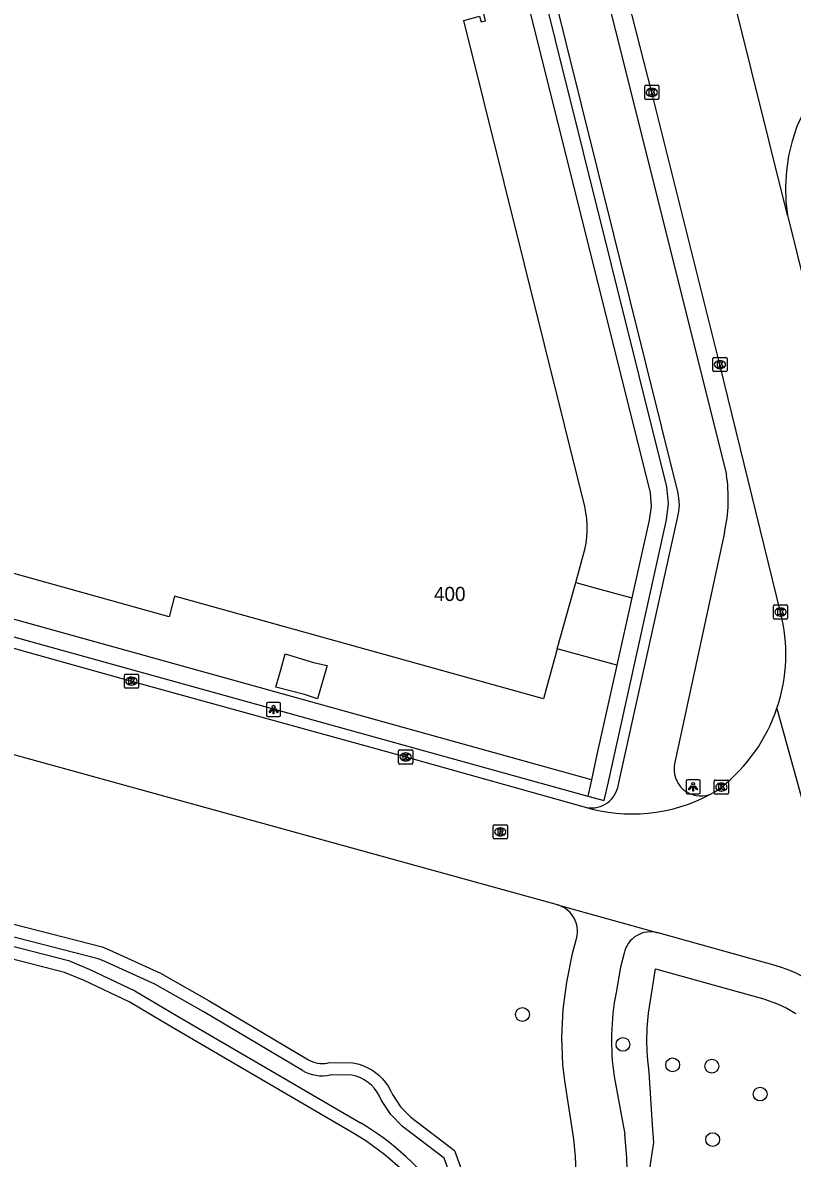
# Model space of a CAD drawing. Extents: x 161389 to 162585, y 388479 to 389761.
# Drawn here: x 162157.9 to 162212.3, y 388784.9 to 388865.1 of the extents above; entities that cross this region are included whole.
import ezdxf

# ---------------------------------------------------------------- set-up
doc = ezdxf.new("R2010")
doc.units = 0
for name, color, linetype in [('IMGEO_Berm_groen', 7, 'Continuous'), ('IMGEO_Boom', 7, 'Continuous'), ('IMGEO_Fietspad_gesloten', 7, 'Continuous'), ('IMGEO_Groenvoorziening', 7, 'Continuous'), ('IMGEO_Kolk', 7, 'Continuous'), ('IMGEO_Lage_trafo', 7, 'Continuous'), ('IMGEO_Lichtpunt', 7, 'Continuous'), ('IMGEO_Pand', 7, 'Continuous'), ('IMGEO_Pand_nummerreeks', 7, 'Continuous'), ('IMGEO_Rijbaan_lokaal_gesloten', 7, 'Continuous'), ('IMGEO_Rioolput', 7, 'Continuous'), ('IMGEO_Voetpad_open', 7, 'Continuous'), ('IMGEO_Waterloop', 7, 'Continuous')]:
    doc.layers.add(name, color=color, linetype=linetype)

msp = doc.modelspace()

# ---------------------------------------------------------------- linework, layer by layer
at = {"layer": 'IMGEO_Berm_groen'}
msp.add_lwpolyline([(162202.114, 388783.702), (162202.484, 388786.004), (162202.374, 388787.24), (162202.153, 388790.947), (162202.031, 388792.052), (162201.988, 388793.08), (162202.013, 388794.111), (162202.107, 388795.136), (162202.604, 388798.273), (162210.309, 388796.119), (162210.472, 388796.068), (162211.203, 388795.801), (162211.87, 388795.491), (162212.509, 388795.125)], dxfattribs=at)
at = {"layer": 'IMGEO_Boom'}
for centre in [(162193.192, 388795.045), (162200.292, 388792.933), (162203.803, 388791.484), (162206.574, 388791.398), (162209.981, 388789.423), (162206.633, 388786.205)]:
    msp.add_circle(centre, 0.489, dxfattribs=at)
at = {"layer": 'IMGEO_Fietspad_gesloten'}
for points in [[(162204.161, 388831.979), (162188.36, 388895.556)], [(162191.915, 388895.933), (162207.606, 388833.207)], [(162199.926, 388811.086), (162200.168, 388812.177), (162204.151, 388830.116)], [(162207.474, 388829.109), (162203.944, 388812.767)], [(162197.064, 388782.261), (162196.952, 388785.015), (162196.823, 388786.236), (162196.189, 388790.366), (162196.057, 388791.508), (162195.972, 388793.453), (162196.061, 388795.397), (162196.323, 388797.325), (162196.735, 388799.351), (162196.994, 388800.318), (162197.039, 388800.488), (162197.069, 388800.661), (162197.083, 388800.836), (162197.081, 388801.012), (162197.064, 388801.186), (162197.031, 388801.359), (162196.983, 388801.528), (162196.92, 388801.692), (162196.843, 388801.85), (162196.752, 388802), (162196.648, 388802.141), (162196.531, 388802.273), (162196.404, 388802.393), (162196.266, 388802.502), (162196.118, 388802.598), (162195.963, 388802.681), (162195.801, 388802.749), (162195.671, 388802.792)], [(162200.371, 388799.377), (162200.112, 388798.397), (162199.808, 388796.6)], [(162199.668, 388790.673), (162200.422, 388786.594)]]:
    msp.add_lwpolyline(points, dxfattribs=at)
for centre, radius, start, end in [((162196.527, 388831.513), 11.207, 347.61514, 8.69505), ((162200.631, 388831.066), 3.646, 344.89022, 14.49469), ((162205.803, 388812.381), 1.899, 168.25765, 289.15512), ((162198.075, 388811.547), 1.907, 254.42232, 346.00308), ((162202.261, 388798.955), 1.937, 74.75853, 167.40051), ((162217.393, 388793.219), 17.907, 169.1183, 188.17546), ((162163.354, 388782.698), 37.273, 345.55573, 5.99964)]:
    msp.add_arc(centre, radius, start, end, dxfattribs=at)
at = {"layer": 'IMGEO_Groenvoorziening'}
for points in [[(162133.461, 388807.522), (162163.504, 388799.815), (162163.994, 388799.622), (162167.615, 388797.975), (162171.074, 388796.012), (162178.078, 388791.853), (162178.229, 388791.773), (162178.386, 388791.706), (162178.548, 388791.653), (162178.715, 388791.616), (162178.884, 388791.593), (162179.055, 388791.586), (162179.225, 388791.594), (162179.394, 388791.617), (162179.528, 388791.646), (162181.221, 388791.631), (162181.333, 388791.61), (162181.653, 388791.53), (162181.964, 388791.422), (162182.265, 388791.286), (162182.552, 388791.124), (162182.823, 388790.937), (162183.077, 388790.727), (162183.311, 388790.495), (162183.523, 388790.242), (162183.711, 388789.972), (162183.875, 388789.686), (162184.013, 388789.387), (162184.582, 388788.521), (162185.306, 388787.78), (162188.39, 388785.424), (162193.632, 388770.975)], [(162184.71, 388784.039), (162183.465, 388785.137), (162182.128, 388786.119), (162181.291, 388786.646), (162168.421, 388794.144), (162165.402, 388795.939), (162162.235, 388797.457), (162160.843, 388798.018), (162131.299, 388805.617)]]:
    msp.add_lwpolyline(points, dxfattribs=at)
at = {"layer": 'IMGEO_Kolk'}
for p, q in [((162201.833, 388859.773), (162201.833, 388860.625)), ((162201.908, 388860.699), (162202.76, 388860.699)), ((162202.321, 388860.479), (162202.346, 388860.479)), ((162202.834, 388860.625), (162202.834, 388859.773)), ((162202.76, 388859.699), (162201.908, 388859.699)), ((162202.344, 388859.919), (162202.319, 388859.919)), ((162206.646, 388840.544), (162206.646, 388841.396)), ((162206.721, 388841.47), (162207.573, 388841.47)), ((162207.134, 388841.25), (162207.159, 388841.25)), ((162207.647, 388841.396), (162207.647, 388840.544)), ((162207.573, 388840.47), (162206.721, 388840.47)), ((162207.157, 388840.69), (162207.132, 388840.69)), ((162210.923, 388823.056), (162210.923, 388823.908)), ((162210.998, 388823.982), (162211.85, 388823.982)), ((162211.434, 388823.202), (162211.409, 388823.202)), ((162211.411, 388823.762), (162211.436, 388823.762)), ((162211.924, 388823.908), (162211.924, 388823.056)), ((162211.85, 388822.982), (162210.998, 388822.982)), ((162165.075, 388818.173), (162165.075, 388819.025)), ((162165.15, 388819.099), (162166.002, 388819.099)), ((162165.563, 388818.879), (162165.588, 388818.879)), ((162166.076, 388819.025), (162166.076, 388818.173)), ((162166.002, 388818.099), (162165.15, 388818.099)), ((162165.586, 388818.319), (162165.561, 388818.319)), ((162184.444, 388812.818), (162184.444, 388813.67)), ((162184.519, 388813.744), (162185.371, 388813.744)), ((162185.445, 388813.67), (162185.445, 388812.818)), ((162184.955, 388812.964), (162184.93, 388812.964)), ((162184.932, 388813.524), (162184.957, 388813.524)), ((162185.371, 388812.744), (162184.519, 388812.744)), ((162206.748, 388810.687), (162206.748, 388811.539)), ((162206.823, 388811.613), (162207.675, 388811.613)), ((162207.236, 388811.393), (162207.261, 388811.393)), ((162207.749, 388811.539), (162207.749, 388810.687)), ((162207.675, 388810.613), (162206.823, 388810.613)), ((162207.259, 388810.833), (162207.234, 388810.833))]:
    msp.add_line(p, q, dxfattribs=at)
for points in [[(162201.833, 388859.773), (162201.833, 388860.625)], [(162201.908, 388860.699), (162202.76, 388860.699)], [(162202.154, 388860.399), (162202.277, 388860.399), (162202.277, 388860.248), (162202.407, 388860.399), (162202.571, 388860.399), (162202.425, 388860.248), (162202.578, 388859.999), (162202.426, 388859.999), (162202.341, 388860.163), (162202.277, 388860.096), (162202.277, 388859.999), (162202.154, 388859.999), (162202.154, 388860.399)], [(162202.834, 388860.625), (162202.834, 388859.773)], [(162202.76, 388859.699), (162201.908, 388859.699)], [(162206.646, 388840.544), (162206.646, 388841.396)], [(162206.721, 388841.47), (162207.573, 388841.47)], [(162206.967, 388841.17), (162207.09, 388841.17), (162207.09, 388841.019), (162207.22, 388841.17), (162207.384, 388841.17), (162207.238, 388841.019), (162207.391, 388840.77), (162207.239, 388840.77), (162207.154, 388840.934), (162207.09, 388840.867), (162207.09, 388840.77), (162206.967, 388840.77), (162206.967, 388841.17)], [(162207.647, 388841.396), (162207.647, 388840.544)], [(162207.573, 388840.47), (162206.721, 388840.47)], [(162210.923, 388823.056), (162210.923, 388823.908)], [(162210.998, 388823.982), (162211.85, 388823.982)], [(162211.244, 388823.682), (162211.367, 388823.682), (162211.367, 388823.531), (162211.497, 388823.682), (162211.661, 388823.682), (162211.515, 388823.531), (162211.668, 388823.282), (162211.516, 388823.282), (162211.431, 388823.446), (162211.367, 388823.379), (162211.367, 388823.282), (162211.244, 388823.282), (162211.244, 388823.682)], [(162211.924, 388823.908), (162211.924, 388823.056)], [(162211.85, 388822.982), (162210.998, 388822.982)], [(162165.075, 388818.173), (162165.075, 388819.025)], [(162165.15, 388819.099), (162166.002, 388819.099)], [(162165.396, 388818.799), (162165.519, 388818.799), (162165.519, 388818.648), (162165.649, 388818.799), (162165.813, 388818.799), (162165.667, 388818.648), (162165.82, 388818.399), (162165.668, 388818.399), (162165.583, 388818.563), (162165.519, 388818.496), (162165.519, 388818.399), (162165.396, 388818.399), (162165.396, 388818.799)], [(162166.076, 388819.025), (162166.076, 388818.173)], [(162166.002, 388818.099), (162165.15, 388818.099)], [(162184.444, 388812.818), (162184.444, 388813.67)], [(162184.519, 388813.744), (162185.371, 388813.744)], [(162185.445, 388813.67), (162185.445, 388812.818)], [(162184.765, 388813.444), (162184.888, 388813.444), (162184.888, 388813.293), (162185.018, 388813.444), (162185.182, 388813.444), (162185.036, 388813.293), (162185.189, 388813.044), (162185.037, 388813.044), (162184.952, 388813.208), (162184.888, 388813.141), (162184.888, 388813.044), (162184.765, 388813.044), (162184.765, 388813.444)], [(162185.371, 388812.744), (162184.519, 388812.744)], [(162206.748, 388810.687), (162206.748, 388811.539)], [(162206.823, 388811.613), (162207.675, 388811.613)], [(162207.069, 388811.313), (162207.192, 388811.313), (162207.192, 388811.162), (162207.322, 388811.313), (162207.486, 388811.313), (162207.34, 388811.162), (162207.493, 388810.913), (162207.341, 388810.913), (162207.256, 388811.077), (162207.192, 388811.01), (162207.192, 388810.913), (162207.069, 388810.913), (162207.069, 388811.313)], [(162207.749, 388811.539), (162207.749, 388810.687)], [(162207.675, 388810.613), (162206.823, 388810.613)]]:
    msp.add_lwpolyline(points, dxfattribs=at)
for centre, start, end in [((162201.91, 388860.623), 91.55205, 178.44795), ((162201.91, 388860.623), 91.55205, 178.44795), ((162202.758, 388860.623), 1.55205, 88.44795), ((162202.758, 388860.623), 1.55205, 88.44795), ((162201.91, 388859.775), 181.55205, 268.44795), ((162201.91, 388859.775), 181.55205, 268.44795), ((162202.758, 388859.775), 271.55205, 358.44795), ((162202.758, 388859.775), 271.55205, 358.44795), ((162206.723, 388841.394), 91.55205, 178.44795), ((162206.723, 388841.394), 91.55205, 178.44795), ((162207.571, 388841.394), 1.55205, 88.44795), ((162207.571, 388841.394), 1.55205, 88.44795), ((162206.723, 388840.546), 181.55205, 268.44795), ((162206.723, 388840.546), 181.55205, 268.44795), ((162207.571, 388840.546), 271.55205, 358.44795), ((162207.571, 388840.546), 271.55205, 358.44795), ((162211, 388823.906), 91.55205, 178.44795), ((162211, 388823.906), 91.55205, 178.44795), ((162211.848, 388823.906), 1.55205, 88.44795), ((162211.848, 388823.906), 1.55205, 88.44795), ((162211, 388823.058), 181.55205, 268.44795), ((162211, 388823.058), 181.55205, 268.44795), ((162211.848, 388823.058), 271.55205, 358.44795), ((162211.848, 388823.058), 271.55205, 358.44795), ((162165.152, 388819.023), 91.55205, 178.44795), ((162165.152, 388819.023), 91.55205, 178.44795), ((162166, 388819.023), 1.55205, 88.44795), ((162166, 388819.023), 1.55205, 88.44795), ((162165.152, 388818.175), 181.55205, 268.44795), ((162165.152, 388818.175), 181.55205, 268.44795), ((162166, 388818.175), 271.55205, 358.44795), ((162166, 388818.175), 271.55205, 358.44795), ((162184.521, 388813.668), 91.55205, 178.44795), ((162184.521, 388813.668), 91.55205, 178.44795), ((162185.369, 388813.668), 1.55205, 88.44795), ((162185.369, 388813.668), 1.55205, 88.44795), ((162184.521, 388812.82), 181.55205, 268.44795), ((162184.521, 388812.82), 181.55205, 268.44795), ((162185.369, 388812.82), 271.55205, 358.44795), ((162185.369, 388812.82), 271.55205, 358.44795), ((162206.825, 388811.537), 91.55205, 178.44795), ((162206.825, 388811.537), 91.55205, 178.44795), ((162207.673, 388811.537), 1.55205, 88.44795), ((162207.673, 388811.537), 1.55205, 88.44795), ((162206.825, 388810.689), 181.55205, 268.44795), ((162206.825, 388810.689), 181.55205, 268.44795), ((162207.673, 388810.689), 271.55205, 358.44795), ((162207.673, 388810.689), 271.55205, 358.44795)]:
    msp.add_arc(centre, 0.0765, start, end, dxfattribs=at)
for centre, major_axis, ratio, start_param, end_param in [((162202.32, 388860.199), (-0.387, 0.002), 0.722429, 4.712389, 7.853982), ((162202.345, 388860.199), (-0.39, 0.002), 0.717154, 1.570796, 4.712389), ((162207.133, 388840.97), (-0.387, 0.002), 0.722429, 4.712389, 7.853982), ((162207.158, 388840.97), (-0.39, 0.002), 0.717154, 1.570796, 4.712389), ((162211.41, 388823.482), (-0.387, 0.002), 0.722429, 4.712389, 7.853982), ((162211.435, 388823.482), (-0.39, 0.002), 0.717154, 1.570796, 4.712389), ((162165.562, 388818.599), (-0.387, 0.002), 0.722429, 4.712389, 7.853982), ((162165.587, 388818.599), (-0.39, 0.002), 0.717154, 1.570796, 4.712389), ((162184.931, 388813.244), (-0.387, 0.002), 0.722429, 4.712389, 7.853982), ((162184.956, 388813.244), (-0.39, 0.002), 0.717154, 1.570796, 4.712389), ((162207.235, 388811.113), (-0.387, 0.002), 0.722429, 4.712389, 7.853982), ((162207.26, 388811.113), (-0.39, 0.002), 0.717154, 1.570796, 4.712389)]:
    msp.add_ellipse(centre, major_axis=major_axis, ratio=ratio, start_param=start_param, end_param=end_param, dxfattribs=at)
at = {"layer": 'IMGEO_Lage_trafo'}
msp.add_lwpolyline([(162178.71, 388817.347), (162177.79, 388817.665), (162175.78, 388818.164), (162176.135, 388819.39), (162176.443, 388820.531), (162178.446, 388819.908), (162179.399, 388819.704), (162178.71, 388817.347)], dxfattribs=at)
at = {"layer": 'IMGEO_Lichtpunt'}
for p, q in [((162175.117, 388816.996), (162175.117, 388816.189)), ((162175.117, 388816.996), (162175.117, 388816.189)), ((162176.019, 388817.091), (162175.211, 388817.091)), ((162176.019, 388817.091), (162175.211, 388817.091)), ((162176.113, 388816.189), (162176.113, 388816.996)), ((162176.113, 388816.189), (162176.113, 388816.996)), ((162175.211, 388816.095), (162176.019, 388816.095)), ((162175.211, 388816.095), (162176.019, 388816.095)), ((162204.749, 388811.541), (162204.749, 388810.734)), ((162204.749, 388811.541), (162204.749, 388810.734)), ((162205.651, 388811.636), (162204.843, 388811.636)), ((162205.651, 388811.636), (162204.843, 388811.636)), ((162205.745, 388810.734), (162205.745, 388811.541)), ((162205.745, 388810.734), (162205.745, 388811.541)), ((162204.843, 388810.64), (162205.651, 388810.64)), ((162204.843, 388810.64), (162205.651, 388810.64))]:
    msp.add_line(p, q, dxfattribs=at)
for points in [[(162175.491, 388816.66), (162175.53, 388816.632), (162175.342, 388816.37), (162175.304, 388816.397), (162175.491, 388816.66)], [(162175.593, 388816.612), (162175.64, 388816.612), (162175.64, 388816.29), (162175.593, 388816.29), (162175.593, 388816.612)], [(162175.703, 388816.632), (162175.741, 388816.659), (162175.928, 388816.397), (162175.889, 388816.369), (162175.703, 388816.632)], [(162205.123, 388811.205), (162205.162, 388811.177), (162204.974, 388810.915), (162204.936, 388810.942), (162205.123, 388811.205)], [(162205.225, 388811.157), (162205.272, 388811.157), (162205.272, 388810.835), (162205.225, 388810.835), (162205.225, 388811.157)], [(162205.335, 388811.177), (162205.373, 388811.204), (162205.56, 388810.942), (162205.521, 388810.914), (162205.335, 388811.177)]]:
    msp.add_lwpolyline(points, dxfattribs=at)
for centre in [(162175.616, 388816.794), (162205.248, 388811.339)]:
    msp.add_circle(centre, 0.0994, dxfattribs=at)
for centre, start, end in [((162175.211, 388816.996), 90, 180), ((162175.211, 388816.996), 90, 180), ((162176.019, 388816.996), 0, 90), ((162176.019, 388816.996), 0, 90), ((162175.211, 388816.189), 180, 270), ((162175.211, 388816.189), 180, 270), ((162176.019, 388816.189), 270, 0), ((162176.019, 388816.189), 270, 360), ((162204.843, 388811.541), 90, 180), ((162204.843, 388811.541), 90, 180), ((162205.651, 388811.541), 0, 90), ((162205.651, 388811.541), 0, 90), ((162204.843, 388810.734), 180, 270), ((162204.843, 388810.734), 180, 270), ((162205.651, 388810.734), 270, 0), ((162205.651, 388810.734), 270, 360)]:
    msp.add_arc(centre, 0.0946, start, end, dxfattribs=at)
at = {"layer": 'IMGEO_Pand'}
for points in [[(162197.59, 388830.934), (162189.064, 388865.285), (162190.162, 388865.576), (162190.288, 388865.174), (162190.591, 388865.254), (162183.364, 388894.315)], [(162195.654, 388820.875), (162194.672, 388817.342), (162168.624, 388824.595), (162168.229, 388823.15), (162146.531, 388829.196), (162146.475, 388829.422)], [(162196.957, 388825.564), (162197.491, 388827.486)], [(162195.654, 388820.875), (162196.957, 388825.564)]]:
    msp.add_lwpolyline(points, dxfattribs=at)
msp.add_arc((162191.237, 388829.391), 6.538, 343.05875, 13.65196, dxfattribs=at)
at = {"layer": 'IMGEO_Rijbaan_lokaal_gesloten'}
for points in [[(162211.426, 388823.482), (162207.148, 388840.97), (162202.335, 388860.2), (162200.937, 388865.633), (162193.265, 388896.286)], [(162211.929, 388851.522), (162204.281, 388882.203)], [(162214.139, 388860.594), (162213.538, 388859.704), (162213.02, 388858.764), (162212.587, 388857.781), (162212.244, 388856.763), (162211.993, 388855.719), (162211.837, 388854.657), (162211.776, 388853.584), (162211.811, 388852.511), (162211.929, 388851.522)], [(162211.929, 388851.522), (162216.475, 388833.075)], [(162144.648, 388824.432), (162146.944, 388823.8), (162165.575, 388818.598), (162184.945, 388813.244), (162197.563, 388809.71)], [(162195.671, 388802.792), (162140.186, 388818.105), (162139.775, 388818.192), (162138.364, 388818.491), (162135.196, 388819.162), (162130.132, 388819.769), (162125.034, 388819.921), (162120.283, 388819.652), (162114.064, 388819.011), (162107.927, 388817.816), (162101.922, 388816.079), (162098.832, 388814.951), (162097.873, 388814.565), (162080.428, 388807.257)], [(162211.175, 388816.678), (162217.643, 388793.25)], [(162206.426, 388810.587), (162206.742, 388810.746), (162207.039, 388810.938), (162207.251, 388811.113)], [(162195.671, 388802.792), (162202.77, 388800.823)], [(162211.048, 388798.507), (162202.77, 388800.823)]]:
    msp.add_lwpolyline(points, dxfattribs=at)
for centre, radius, start, end in [((162199.845, 388820.503), 11.958, 341.34692, 14.42771), ((162199.84, 388820.505), 11.963, 308.27708, 341.34596), ((162200.933, 388820.873), 11.66, 253.19917, 298.10296), ((162207.858, 388787.74), 11.229, 29.384, 73.49797)]:
    msp.add_arc(centre, radius, start, end, dxfattribs=at)
at = {"layer": 'IMGEO_Rioolput'}
for p, q in [((162191.13, 388807.523), (162191.13, 388808.375)), ((162191.205, 388808.449), (162192.057, 388808.449)), ((162191.618, 388808.229), (162191.643, 388808.229)), ((162192.131, 388808.375), (162192.131, 388807.523)), ((162192.057, 388807.449), (162191.205, 388807.449)), ((162191.641, 388807.669), (162191.616, 388807.669))]:
    msp.add_line(p, q, dxfattribs=at)
for points in [[(162191.13, 388807.523), (162191.13, 388808.375)], [(162191.205, 388808.449), (162192.057, 388808.449)], [(162191.719, 388808.147), (162191.467, 388808.149), (162191.467, 388807.749)], [(162191.645, 388808.068), (162191.591, 388808.068), (162191.591, 388807.987)], [(162191.591, 388807.987), (162191.643, 388807.987)], [(162192.131, 388808.375), (162192.131, 388807.523)], [(162192.057, 388807.449), (162191.205, 388807.449)], [(162191.467, 388807.749), (162191.591, 388807.749), (162191.591, 388807.911), (162191.602, 388807.911)], [(162191.649, 388807.882), (162191.72, 388807.749), (162191.86, 388807.749), (162191.795, 388807.875)]]:
    msp.add_lwpolyline(points, dxfattribs=at)
for centre, radius, start, end in [((162191.207, 388808.373), 0.0765, 91.55205, 178.44795), ((162191.207, 388808.373), 0.0765, 91.55205, 178.44795), ((162191.627, 388808.176), 0.19, 274.7715, 282.96867), ((162191.651, 388807.972), 0.0964, 77.00612, 93.18647), ((162191.665, 388808.029), 0.0378, 276.66336, 79.67722), ((162191.718, 388808.037), 0.109, 350.36119, 89.41601), ((162191.716, 388808.037), 0.112, 277.58423, 350.98172), ((162192.055, 388808.373), 0.0765, 1.55205, 88.44795), ((162192.055, 388808.373), 0.0765, 1.55205, 88.44795), ((162191.207, 388807.525), 0.0765, 181.55205, 268.44795), ((162191.207, 388807.525), 0.0765, 181.55205, 268.44795), ((162191.601, 388807.858), 0.0533, 26.02933, 88.69889), ((162191.7, 388807.822), 0.108, 29.51342, 73.79051), ((162192.055, 388807.525), 0.0765, 271.55205, 358.44795), ((162192.055, 388807.525), 0.0765, 271.55205, 358.44795)]:
    msp.add_arc(centre, radius, start, end, dxfattribs=at)
for centre, major_axis, ratio, start_param, end_param in [((162191.617, 388807.949), (-0.387, 0.002), 0.722429, 4.712389, 7.853982), ((162191.642, 388807.949), (-0.39, 0.002), 0.717154, 1.570796, 4.712389)]:
    msp.add_ellipse(centre, major_axis=major_axis, ratio=ratio, start_param=start_param, end_param=end_param, dxfattribs=at)
at = {"layer": 'IMGEO_Voetpad_open'}
for points in [[(162186.448, 388895.081), (162202.214, 388831.899), (162202.283, 388830.935), (162202.145, 388829.978), (162200.919, 388824.477)], [(162197.816, 388810.478), (162198.971, 388810.158), (162199.262, 388811.491), (162203.372, 388829.992), (162203.503, 388831.163), (162203.383, 388832.334), (162187.678, 388895.387)], [(162198.067, 388811.633), (162144.08, 388826.632)], [(162144.44, 388825.28), (162197.816, 388810.478)], [(162196.957, 388825.564), (162198.402, 388825.168), (162200.919, 388824.477)], [(162200.919, 388824.477), (162199.861, 388819.726)], [(162199.861, 388819.726), (162197.11, 388820.477), (162195.654, 388820.875)], [(162199.861, 388819.726), (162198.455, 388813.42), (162198.067, 388811.633)], [(162198.067, 388811.633), (162197.816, 388810.478)]]:
    msp.add_lwpolyline(points, dxfattribs=at)
at = {"layer": 'IMGEO_Waterloop'}
for points in [[(162177.65, 388791.09), (162170.635, 388795.256), (162167.217, 388797.195), (162163.652, 388798.817), (162163.234, 388798.981), (162133.167, 388806.694), (162128.042, 388809.049)], [(162127.395, 388807.421), (162128.792, 388807.093), (162131.506, 388806.467), (162161.117, 388798.851), (162162.588, 388798.258), (162165.815, 388796.711), (162168.865, 388794.898), (162181.744, 388787.394)], [(162181.136, 388790.757), (162179.618, 388790.771)], [(162183.935, 388699.637), (162183.687, 388700.43), (162183.794, 388702.552), (162184.455, 388714.365), (162185.037, 388717.142), (162184.552, 388723.272), (162185.295, 388735.972), (162187.332, 388750.153), (162188.703, 388756.652), (162192.714, 388770.941), (162187.655, 388784.885), (162184.725, 388787.123), (162183.897, 388787.97), (162183.246, 388788.961), (162183.097, 388789.284)]]:
    msp.add_lwpolyline(points, dxfattribs=at)
for centre, radius, start, end in [((162179.046, 388793.472), 2.761, 239.62613, 281.95949), ((162180.599, 388788.001), 2.808, 27.19291, 78.98319), ((162171.764, 388770.599), 19.536, 35.57668, 59.28137)]:
    msp.add_arc(centre, radius, start, end, dxfattribs=at)

# ---------------------------------------------------------------- texts
at = {"layer": 'IMGEO_Pand_nummerreeks'}
msp.add_text('400', height=1, dxfattribs=at).set_placement((162186.942, 388824.262))

doc.saveas('drawing.dxf')
